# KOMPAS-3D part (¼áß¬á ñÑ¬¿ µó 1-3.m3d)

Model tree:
1. Эскиз:1
2. Операция выдавливания:24
     Толщина стенки 2 = 14; Расстояние 1 = 0.6
3. Эскиз:22
4. Операция выдавливания:25
     Толщина стенки 1 = 7; Толщина стенки 2 = 6; Расстояние 1 = 0.6; Расстояние 2 = 0.6
5. Эскиз:23
6. Операция выдавливания:26
     Толщина стенки 1 = 6; Толщина стенки 2 = 6; Расстояние 1 = 0.6
7. Эскиз:26
8. Вырезать элемент выдавливания:3
     Толщина стенки 1 = 7; Расстояние 1 = 10
